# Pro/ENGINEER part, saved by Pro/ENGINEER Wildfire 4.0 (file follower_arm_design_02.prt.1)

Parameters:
  METRIC = "NO"

Other parameters: PITCH, DRILL_DIAMETER, THREAD_DIAMETER, THREADS_PER_INCH, THREAD_DEPTH, THREAD_LENGTH, DRILL_POINT_ANGLE, DRILL_DEPTH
